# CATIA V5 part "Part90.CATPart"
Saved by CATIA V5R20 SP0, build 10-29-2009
Part number: FA 053000-2
Revision: ANY
Definition: UNKNOWN
Nomenclature: FA 053000-2
Source: Unknown
Bounding box of the stored display mesh (mm): x -1.5 to 1.5, y 0 to 3.7, z -1.5 to 1.5
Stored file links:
  C:\Users\Utente\Desktop\IO LAVORO\3D X SITO CF\CUMSA\3D files FA\FA 053012-21\Part90.CATPart

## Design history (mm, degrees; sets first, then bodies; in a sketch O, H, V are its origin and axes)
Body1 "Cortar-Extruir1" (main body)
  Solid1: solid without history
